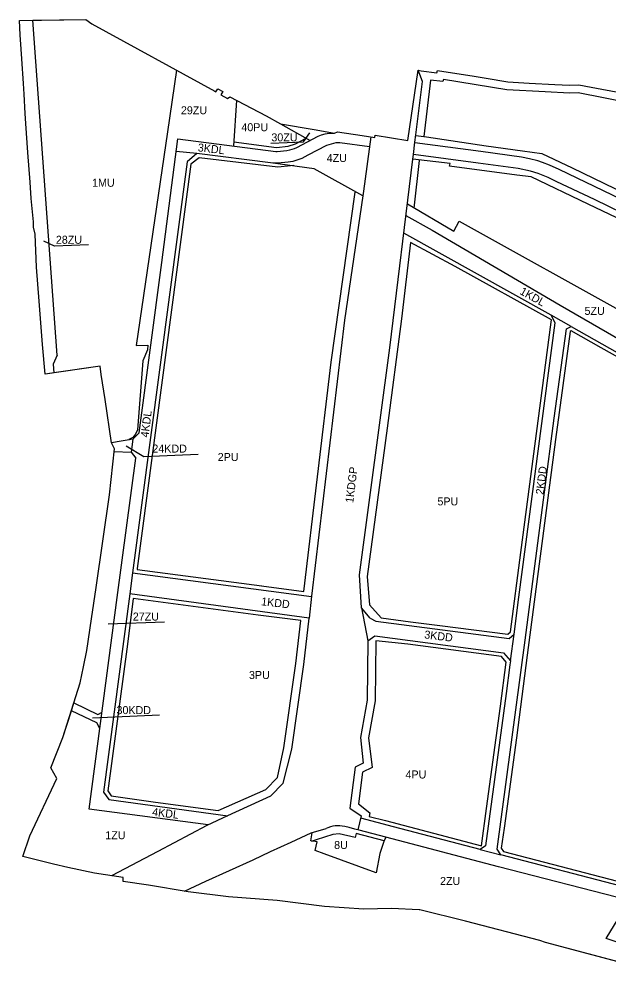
# Model space of a CAD drawing. Extents: x 7428203 to 7432868, y 5542672 to 5545406.
# Drawn here: x 7428203 to 7428940, y 5544072 to 5545281 of the extents above; entities that cross this region are included whole.
import ezdxf

# ---------------------------------------------------------------- set-up
doc = ezdxf.new("R2010")
doc.units = 0
for name, color, linetype in [('granica_planu', 7, 'Continuous'), ('linie_rozgraniczajace', 7, 'Continuous'), ('linie_zabudowy_nieprzekraczalne', 7, 'Continuous'), ('oznaczenia_przeznaczen', 7, 'Continuous')]:
    doc.layers.add(name, color=color, linetype=linetype)

msp = doc.modelspace()

# ---------------------------------------------------------------- linework, layer by layer
at = {"layer": 'granica_planu'}
msp.add_lwpolyline([(7428976.57, 5544096.41), (7428860.8, 5544127.52), (7428854.01, 5544130), (7428760.75, 5544154.04), (7428703.73, 5544168.24), (7428702.84, 5544168.29), (7428668.51, 5544170.04), (7428651.15, 5544169.49), (7428633.78, 5544168.93), (7428584.72, 5544172.19), (7428525.4, 5544180.04), (7428464.81, 5544184.55), (7428414.41, 5544190.57), (7428364.61, 5544199.09), (7428332.93, 5544203.75), (7428333.18, 5544208.54), (7428297.27, 5544213.91), (7428264.18, 5544221.13), (7428246.26, 5544225.05), (7428227.65, 5544229.82), (7428211.18, 5544234.03), (7428207.81, 5544234.91), (7428216.65, 5544260.74), (7428250.38, 5544332.47), (7428242.63, 5544345.7), (7428257.92, 5544383.71), (7428279.49, 5544451.84), (7428283.67, 5544472.01), (7428287.85, 5544492.18), (7428293.63, 5544531.64), (7428299.42, 5544571.11), (7428307.66, 5544628.99), (7428315.9, 5544686.88), (7428322.14, 5544744.45), (7428318.62, 5544751.58), (7428310.47, 5544805.9), (7428305.82, 5544836.94), (7428304.21, 5544847.68), (7428235.61, 5544837.59), (7428232.37, 5544874.57), (7428228.23, 5544928.73), (7428224.8, 5544971.21), (7428223.17, 5545012.45), (7428221.01, 5545021.19), (7428220.96, 5545027.72), (7428218.36, 5545057.21), (7428216.77, 5545077.57), (7428213.9, 5545114.42), (7428211.37, 5545150.6), (7428210.73, 5545163.13), (7428209.3, 5545187.57), (7428208.58, 5545200.8), (7428206.55, 5545231.54), (7428205.75, 5545243.51), (7428204.57, 5545261.47), (7428203.38, 5545279.44), (7428286.65, 5545280.95), (7428294.08, 5545275.54), (7428447.54, 5545191.05), (7428448.77, 5545190.38), (7428451.22, 5545194.3), (7428457.59, 5545190.79), (7428455.34, 5545186.6), (7428463.51, 5545182.06), (7428466.26, 5545184.02), (7428511.95, 5545160.26), (7428529.59, 5545150.37), (7428571.85, 5545143.2), (7428597.2, 5545138.9), (7428601.15, 5545140.18), (7428631.6, 5545135.8), (7428647.7, 5545133.49), (7428648.02, 5545136.23), (7428688.7, 5545129.56), (7428701.69, 5545217.27), (7428705.62, 5545216.46), (7428725.13, 5545214.15), (7428725.96, 5545217.18), (7428771.73, 5545209.75), (7428786.74, 5545207.32), (7428813.69, 5545202.94), (7428840.31, 5545201.4), (7428872.5, 5545199.53), (7428891.02, 5545198.75), (7428902.46, 5545199.05), (7428917.87, 5545196.3), (7428955.81, 5545189.3)], dxfattribs=at)
at = {"layer": 'linie_rozgraniczajace'}
for p, q in [((7428204.57, 5545261.47), (7428203.38, 5545279.44)), ((7428286.65, 5545280.95), (7428294.08, 5545275.54)), ((7428294.08, 5545275.54), (7428447.54, 5545191.05)), ((7428205.75, 5545243.51), (7428204.57, 5545261.47)), ((7428206.55, 5545231.54), (7428205.75, 5545243.51)), ((7428208.58, 5545200.8), (7428206.55, 5545231.54)), ((7428688.7, 5545129.56), (7428701.69, 5545217.27)), ((7428701.69, 5545217.27), (7428705.62, 5545216.46)), ((7428705.62, 5545216.46), (7428725.13, 5545214.15)), ((7428725.13, 5545214.15), (7428725.96, 5545217.18)), ((7428725.96, 5545217.18), (7428771.73, 5545209.75)), ((7428209.3, 5545187.57), (7428208.58, 5545200.8)), ((7428771.73, 5545209.75), (7428786.74, 5545207.32)), ((7428786.74, 5545207.32), (7428813.69, 5545202.94)), ((7428813.69, 5545202.94), (7428840.31, 5545201.4)), ((7428840.31, 5545201.4), (7428872.5, 5545199.53)), ((7428872.5, 5545199.53), (7428891.02, 5545198.75)), ((7428891.02, 5545198.75), (7428902.46, 5545199.05)), ((7428902.46, 5545199.05), (7428917.87, 5545196.3)), ((7428210.73, 5545163.13), (7428209.3, 5545187.57)), ((7428447.54, 5545191.05), (7428448.77, 5545190.38)), ((7428448.77, 5545190.38), (7428451.22, 5545194.3)), ((7428451.22, 5545194.3), (7428457.59, 5545190.79)), ((7428457.59, 5545190.79), (7428455.34, 5545186.6)), ((7428455.34, 5545186.6), (7428463.51, 5545182.06)), ((7428917.87, 5545196.3), (7428955.81, 5545189.3)), ((7428463.51, 5545182.06), (7428466.26, 5545184.02)), ((7428466.26, 5545184.02), (7428511.95, 5545160.26)), ((7428474.82, 5545179.57), (7428470.97, 5545122.84)), ((7428211.37, 5545150.6), (7428210.73, 5545163.13)), ((7428213.9, 5545114.42), (7428211.37, 5545150.6)), ((7428511.95, 5545160.26), (7428529.59, 5545150.37)), ((7428529.59, 5545150.37), (7428571.85, 5545143.2)), ((7428529.59, 5545150.37), (7428566.84, 5545129.46)), ((7428571.85, 5545143.2), (7428597.2, 5545138.9)), ((7428585.67, 5545137.9), (7428590.63, 5545138.64)), ((7428590.63, 5545138.64), (7428597.2, 5545138.9)), ((7428597.2, 5545138.9), (7428601.15, 5545140.18)), ((7428601.15, 5545140.18), (7428631.6, 5545135.8)), ((7428381.26, 5544977.16), (7428401.55, 5545131.8)), ((7428401.55, 5545131.8), (7428523.95, 5545116)), ((7428550.34, 5545120.73), (7428577, 5545134.84)), ((7428577, 5545134.84), (7428581.01, 5545136.68)), ((7428581.01, 5545136.68), (7428585.67, 5545137.9)), ((7428598.85, 5545126.59), (7428593.01, 5545124.97)), ((7428603.85, 5545126.69), (7428598.85, 5545126.59)), ((7428641.1, 5545121.81), (7428603.85, 5545126.69)), ((7428631.6, 5545135.8), (7428647.7, 5545133.49)), ((7428647.7, 5545133.49), (7428648.02, 5545136.23)), ((7428648.02, 5545136.23), (7428688.7, 5545129.56)), ((7428216.77, 5545077.57), (7428213.9, 5545114.42)), ((7428425.38, 5545113.27), (7428399.48, 5545115.99)), ((7428523.95, 5545116), (7428525.6, 5545116)), ((7428525.6, 5545116), (7428537.56, 5545117.17)), ((7428537.56, 5545117.17), (7428541.51, 5545117.82)), ((7428541.51, 5545117.82), (7428547.39, 5545119.75)), ((7428547.39, 5545119.75), (7428550.34, 5545120.73)), ((7428587.34, 5545123.25), (7428563.88, 5545111.05)), ((7428593.01, 5545124.97), (7428587.34, 5545123.25)), ((7428413.01, 5545102.98), (7428344.99, 5544589.32)), ((7428425.38, 5545113.27), (7428413.01, 5545102.98)), ((7428517.38, 5545101.52), (7428425.38, 5545113.27)), ((7428539.46, 5545102.28), (7428526.47, 5545101.12)), ((7428545.09, 5545103.21), (7428539.46, 5545102.28)), ((7428556.34, 5545106.91), (7428545.09, 5545103.21)), ((7428563.88, 5545111.05), (7428556.34, 5545106.91)), ((7428741.66, 5545100.69), (7428695.14, 5545106.15)), ((7428526.47, 5545101.12), (7428517.38, 5545101.52)), ((7428571.72, 5545094.34), (7428517.38, 5545101.52)), ((7428632.77, 5545060.49), (7428571.72, 5545094.34)), ((7428741.11, 5545097.37), (7428741.66, 5545100.69)), ((7428824.91, 5545086.26), (7428741.11, 5545097.37)), ((7428842.91, 5545084.32), (7428824.91, 5545086.26)), ((7428914.24, 5545050.13), (7428842.91, 5545084.32)), ((7428218.36, 5545057.21), (7428216.77, 5545077.57)), ((7428220.96, 5545027.72), (7428218.36, 5545057.21)), ((7428688.36, 5545050.58), (7428746.31, 5545016.37)), ((7429194.36, 5544914.89), (7428914.24, 5545050.13)), ((7428221.01, 5545021.19), (7428220.96, 5545027.72)), ((7428223.17, 5545012.45), (7428221.01, 5545021.19)), ((7428746.31, 5545016.37), (7428752.97, 5545028.91)), ((7428752.97, 5545028.91), (7429178.24, 5544792.55)), ((7428224.8, 5544971.21), (7428223.17, 5545012.45)), ((7428228.23, 5544928.73), (7428224.8, 5544971.21)), ((7428353.04, 5544764.26), (7428381.26, 5544977.16)), ((7428232.37, 5544874.57), (7428228.23, 5544928.73)), ((7428893.15, 5544897.22), (7428868.13, 5544911.33)), ((7428235.61, 5544837.59), (7428232.37, 5544874.57)), ((7428305.82, 5544836.94), (7428304.21, 5544847.68)), ((7428310.47, 5544805.9), (7428305.82, 5544836.94)), ((7428318.62, 5544751.58), (7428310.47, 5544805.9)), ((7428322.14, 5544744.45), (7428318.62, 5544751.58)), ((7428345.22, 5544756.14), (7428342.96, 5544740.16)), ((7428315.9, 5544686.88), (7428322.14, 5544744.45)), ((7428325.79, 5544558.62), (7428348.87, 5544732.75)), ((7428307.66, 5544628.99), (7428315.9, 5544686.88)), ((7428299.42, 5544571.11), (7428307.66, 5544628.99)), ((7428344.99, 5544589.32), (7428341.48, 5544562.94)), ((7428344.99, 5544589.32), (7428568.35, 5544559.65)), ((7428293.63, 5544531.64), (7428299.42, 5544571.11)), ((7428290.72, 5544294.07), (7428325.79, 5544558.62)), ((7428341.48, 5544562.94), (7428308.67, 5544315.36)), ((7428565.65, 5544532.84), (7428341.48, 5544562.94)), ((7428631.09, 5544545.61), (7428638.77, 5544504.44)), ((7428287.85, 5544492.18), (7428293.63, 5544531.64)), ((7428558.86, 5544474.65), (7428565.65, 5544532.84)), ((7428638.77, 5544504.44), (7428647.67, 5544510.77)), ((7428647.67, 5544510.77), (7428808.28, 5544489.37)), ((7428816.99, 5544479.53), (7428821.67, 5544512.69)), ((7428283.67, 5544472.01), (7428287.85, 5544492.18)), ((7428808.28, 5544489.37), (7428816.99, 5544479.53)), ((7428543.8, 5544369.15), (7428558.86, 5544474.65)), ((7428816.5, 5544474.34), (7428811.84, 5544438.61)), ((7428816.99, 5544479.53), (7428816.5, 5544474.34)), ((7428279.49, 5544451.84), (7428283.67, 5544472.01)), ((7428811.84, 5544438.61), (7428785.79, 5544248.05)), ((7428242.63, 5544345.7), (7428257.92, 5544383.71)), ((7428533.25, 5544326.63), (7428543.8, 5544369.15)), ((7428250.38, 5544332.47), (7428242.63, 5544345.7)), ((7428216.65, 5544260.74), (7428250.38, 5544332.47)), ((7428308.67, 5544315.36), (7428315.14, 5544306.06)), ((7428315.14, 5544306.06), (7428463.89, 5544285.68)), ((7428439.41, 5544274.21), (7428290.72, 5544294.07)), ((7428670.93, 5544272), (7428629.95, 5544282.69)), ((7428779.07, 5544243.6), (7428670.93, 5544272)), ((7428207.81, 5544234.91), (7428216.65, 5544260.74)), ((7428661.27, 5544258.91), (7428627.91, 5544267.68)), ((7428785.79, 5544248.05), (7428779.07, 5544243.6)), ((7428211.18, 5544234.03), (7428207.81, 5544234.91)), ((7428227.65, 5544229.82), (7428211.18, 5544234.03)), ((7428779.07, 5544243.6), (7428805.14, 5544236.81)), ((7428246.26, 5544225.05), (7428227.65, 5544229.82)), ((7428264.18, 5544221.13), (7428246.26, 5544225.05)), ((7428297.27, 5544213.91), (7428264.18, 5544221.13)), ((7428333.18, 5544208.54), (7428297.27, 5544213.91)), ((7428332.93, 5544203.75), (7428333.18, 5544208.54)), ((7428364.61, 5544199.09), (7428332.93, 5544203.75)), ((7428414.41, 5544190.57), (7428364.61, 5544199.09)), ((7428464.81, 5544184.55), (7428414.41, 5544190.57)), ((7428525.4, 5544180.04), (7428464.81, 5544184.55)), ((7428584.72, 5544172.19), (7428525.4, 5544180.04)), ((7428633.78, 5544168.93), (7428584.72, 5544172.19)), ((7428651.15, 5544169.49), (7428633.78, 5544168.93)), ((7428668.51, 5544170.04), (7428651.15, 5544169.49)), ((7428702.84, 5544168.29), (7428668.51, 5544170.04)), ((7428703.73, 5544168.24), (7428702.84, 5544168.29)), ((7428760.75, 5544154.04), (7428703.73, 5544168.24)), ((7428854.01, 5544130), (7428760.75, 5544154.04)), ((7428860.8, 5544127.52), (7428854.01, 5544130)), ((7428976.57, 5544096.41), (7428860.8, 5544127.52))]:
    msp.add_line(p, q, dxfattribs=at)
for points in [[(7428203.38, 5545279.44), (7428220.24, 5545279.74), (7428286.65, 5545280.95)], [(7428250.61, 5544861.39), (7428220.24, 5545279.74)], [(7428399.9, 5545217.28), (7428388.59, 5545140.59), (7428349.51, 5544873.25)], [(7428641.76, 5544532.47), (7428631.09, 5544545.61), (7428628.59, 5544586.69), (7428666.41, 5544870.56), (7428695.14, 5545106.15), (7428695.81, 5545111.93), (7428697.64, 5545127.52), (7428698.87, 5545136.61), (7428707.01, 5545203.48), (7428703.82, 5545211.9), (7428701.69, 5545217.27)], [(7428642.78, 5545134.2), (7428633.57, 5545066.36), (7428632.77, 5545060.49)], [(7429066.8, 5545002.44), (7428878, 5545093.23), (7428865.96, 5545098.79), (7428857.25, 5545102.2), (7428851.29, 5545104.05), (7428841.01, 5545106.72), (7428830.84, 5545108.91), (7428779.93, 5545116.01), (7428697.56, 5545126.83)], [(7428698.78, 5545135.91), (7428712.39, 5545133.97), (7428786.67, 5545123.07), (7428832.04, 5545116.79), (7428856.2, 5545113.43), (7428894.3, 5545095.54), (7429080.93, 5545005.11), (7429141.74, 5545005.48), (7429132.6, 5544978.04), (7429206.67, 5544942.98), (7429220.26, 5544939.2), (7429256.65, 5544938.86), (7429264.53, 5544938.12), (7429416.34, 5544933.1), (7429628, 5544926.11), (7429629.2, 5544929.06)], [(7428957.96, 5545038.3), (7428922.02, 5545055.69), (7428875.19, 5545077.96), (7428864.32, 5545083.13), (7428855.79, 5545086.67), (7428851.76, 5545088.25), (7428842, 5545091.16), (7428826.74, 5545094.39), (7428776.93, 5545101.29), (7428695.81, 5545111.93)], [(7428632.77, 5545060.49), (7428609.65, 5544905.04), (7428568.4, 5544560.19), (7428565.65, 5544532.84)], [(7428686.57, 5545035.92), (7428719.44, 5545017.6), (7428879.25, 5544923.88), (7428986.55, 5544861.55)], [(7428641.76, 5544532.47), (7428649.01, 5544528.76), (7428815.39, 5544507.44), (7428821.67, 5544512.69), (7428827.77, 5544559.05), (7428873.05, 5544901.71), (7428868.13, 5544911.33), (7428683.85, 5545013.62)], [(7429198.67, 5544727.47), (7429176.49, 5544739.59), (7429181.27, 5544730.14), (7429139.09, 5544411.72), (7429106.05, 5544162.35), (7429099.14, 5544157.86), (7428955.29, 5544197.85), (7428805.14, 5544236.81), (7428800.36, 5544244.12), (7428835.48, 5544505.35), (7428871.87, 5544782.58), (7428886.98, 5544894.27), (7428893.15, 5544897.22), (7428979.15, 5544848.51), (7428994.76, 5544839.83), (7428990.64, 5544827.77), (7428982.93, 5544761.65), (7428979.22, 5544729.83), (7429033.78, 5544721.61), (7429045.31, 5544798.17), (7429047.66, 5544810.44), (7429085.54, 5544789.39), (7429155.84, 5544750.87), (7429176.49, 5544739.59)], [(7428349.51, 5544873.25), (7428363.86, 5544873.81), (7428363.47, 5544867.85), (7428357.61, 5544854.27), (7428351.03, 5544768.14), (7428348.57, 5544762.51), (7428345.4, 5544758.61), (7428340.26, 5544755.89), (7428340.06, 5544755.29)], [(7428250.61, 5544861.39), (7428245.61, 5544849.98), (7428246.43, 5544839.18)], [(7428304.21, 5544847.68), (7428246.43, 5544839.18), (7428235.61, 5544837.59)], [(7428353.04, 5544764.26), (7428345.22, 5544756.14), (7428318.59, 5544751.76)], [(7428321.77, 5544740.99), (7428342.96, 5544740.16), (7428348.87, 5544732.75)], [(7428638.77, 5544504.44), (7428638.07, 5544430.1), (7428629.67, 5544383.68), (7428632.86, 5544351.61), (7428623.1, 5544346.62), (7428616.46, 5544295.36), (7428630.61, 5544285.45), (7428626.47, 5544268.06)], [(7428257.92, 5544383.71), (7428268.45, 5544416.97), (7428271.6, 5544426.92), (7428279.49, 5544451.84)], [(7428271.6, 5544426.92), (7428301.55, 5544412.33), (7428306.76, 5544415.07)], [(7428304.07, 5544394.81), (7428300.27, 5544402), (7428268.45, 5544416.97)], [(7428533.25, 5544326.63), (7428517.25, 5544310.17), (7428463.57, 5544285.54), (7428437.69, 5544273.41), (7428376.62, 5544241.05), (7428318.69, 5544210.71)], [(7428409.63, 5544191.39), (7428436.56, 5544203.82), (7428495.4, 5544230.51), (7428517.32, 5544241.22), (7428543.21, 5544252.82), (7428568.05, 5544264.25), (7428586.94, 5544269.96)], [(7428627.91, 5544267.68), (7428622.53, 5544269.1), (7428615.51, 5544270.93), (7428609.97, 5544272.15), (7428606.99, 5544272.71), (7428603.84, 5544273.06), (7428601.11, 5544273.16), (7428598.26, 5544273.05), (7428595.12, 5544272.7), (7428592.07, 5544272.11), (7428588.99, 5544270.86), (7428586.94, 5544269.96)], [(7428584.29, 5544238.12), (7428573.13, 5544242.21), (7428575.47, 5544253.06), (7428567.69, 5544254.25), (7428569.27, 5544264.61)], [(7429068.86, 5544072.19), (7429060.22, 5544098.67), (7429018.58, 5544105.27), (7428936.65, 5544132.38), (7428960.84, 5544171.8), (7428964.08, 5544180.06), (7428802.22, 5544221.94), (7428661.3, 5544258.99), (7428659.05, 5544253.72), (7428653.94, 5544238.67), (7428649.37, 5544214.38), (7428584.29, 5544238.12)]]:
    msp.add_lwpolyline(points, dxfattribs=at)
at = {"layer": 'linie_zabudowy_nieprzekraczalne'}
for p, q in [((7428471.31, 5545127.84), (7428524.74, 5545120.94)), ((7428548.38, 5545125.34), (7428561.66, 5545132.37)), ((7428524.74, 5545120.94), (7428539.34, 5545122.37)), ((7428539.34, 5545122.37), (7428548.38, 5545125.34)), ((7428703, 5545104.52), (7428696.16, 5545044.92)), ((7428868.54, 5544905.38), (7428748.02, 5544972.28)), ((7428830.05, 5544614.77), (7428868.1, 5544902.37)), ((7428868.1, 5544902.37), (7428868.54, 5544905.38)), ((7428817.03, 5544515.59), (7428830.05, 5544614.77)), ((7428345.67, 5544557.34), (7428338.36, 5544500.05)), ((7428501.72, 5544536.38), (7428345.67, 5544557.34)), ((7428692.19, 5544528.27), (7428728.65, 5544523.6)), ((7428728.65, 5544523.6), (7428813.86, 5544512.68)), ((7428813.86, 5544512.68), (7428817.03, 5544515.59)), ((7428338.36, 5544500.05), (7428313.91, 5544316.88)), ((7428805.77, 5544484.66), (7428688.67, 5544500.26)), ((7428804.62, 5544422.79), (7428811.81, 5544477.84)), ((7428811.81, 5544477.84), (7428805.77, 5544484.66)), ((7428787.13, 5544294.85), (7428804.62, 5544422.79)), ((7428313.91, 5544316.88), (7428318.23, 5544310.67)), ((7428318.23, 5544310.67), (7428373.45, 5544302.87)), ((7428373.45, 5544302.87), (7428451.93, 5544292.24)), ((7428780.78, 5544248.32), (7428787.13, 5544294.85)), ((7428660.94, 5544279.72), (7428780.78, 5544248.32))]:
    msp.add_line(p, q, dxfattribs=at)
for points in [[(7429616.61, 5544926.59), (7429647.45, 5545018.33), (7429649.37, 5545036.38), (7429583.9, 5545048.39), (7429433.03, 5545062.81), (7429282.53, 5545076.05), (7429087.37, 5545134.55), (7429047.91, 5545146.12), (7429048.68, 5545151.72), (7428964.03, 5545172.65), (7428964.84, 5545176.81), (7428901.68, 5545189.02), (7428890.94, 5545188.75), (7428860.63, 5545190.2), (7428812.6, 5545192.99), (7428733.24, 5545205.87), (7428732.51, 5545203.2), (7428717.24, 5545204.75), (7428708.73, 5545134.37)], [(7428546.29, 5545098.34), (7428526.58, 5545096.11), (7428428.21, 5545107.97), (7428417.72, 5545099.98), (7428350.75, 5544594.72), (7428350.76, 5544593.58), (7428506.32, 5544572.98)], [(7428506.1, 5544573.13), (7428558.94, 5544566.12), (7428593.25, 5544852.39), (7428623.16, 5545064.86)], [(7428748.02, 5544972.28), (7428692.26, 5545001.97), (7428681.15, 5544906.78), (7428662.98, 5544770.19), (7428638.03, 5544584.59), (7428640.88, 5544549.42), (7428655.43, 5544532.97), (7428692.19, 5544528.27)], [(7428451.93, 5544292.24), (7428511.38, 5544318.48), (7428526.08, 5544333.6), (7428533.9, 5544370.56), (7428548.96, 5544476.06), (7428555.27, 5544529.85), (7428501.72, 5544536.38)], [(7428688.67, 5544500.26), (7428648.77, 5544504.34), (7428648.06, 5544429.16), (7428639.76, 5544383.27), (7428644.19, 5544345.88), (7428632.34, 5544340.12), (7428627.2, 5544300.45), (7428641.18, 5544289.39), (7428640.6, 5544284.93), (7428660.94, 5544279.72)], [(7428624.48, 5544263.43), (7428622.94, 5544258.48), (7428603.12, 5544263.08), (7428595.04, 5544262.51), (7428574.28, 5544255.68), (7428568.09, 5544253.65)], [(7428659.32, 5544254.35), (7428624.48, 5544263.43), (7428624.48, 5544263.43)]]:
    msp.add_lwpolyline(points, dxfattribs=at)
msp.add_lwpolyline([(7428892.96, 5544891.59), (7428891.57, 5544890.93), (7428873.42, 5544756.02), (7428838.05, 5544486.51), (7428824.47, 5544383), (7428809.45, 5544270.11), (7428805.6, 5544245.24), (7428808.27, 5544241.17), (7428960.48, 5544201.62), (7429063.14, 5544173.58), (7429098.37, 5544163.32), (7429101.4, 5544165.29), (7429115.21, 5544269.13), (7429156.74, 5544584.47), (7429176.11, 5544729.27), (7429172.73, 5544735.95), (7429073.35, 5544790.45), (7428930.42, 5544870.37)], close=True, dxfattribs=at)
at = {"layer": 'oznaczenia_przeznaczen'}
for p, q in [((7428314.51, 5544525.39), (7428384.85, 5544528.24)), ((7428294.84, 5544408.27), (7428378.63, 5544411.67))]:
    msp.add_line(p, q, dxfattribs=at)
for points in [[(7428517.55, 5545126.15), (7428558.68, 5545127.82), (7428566.19, 5545139.18)], [(7428289.96, 5544999.35), (7428247.48, 5544997.62), (7428234.15, 5545003.69)], [(7428426.67, 5544737.07), (7428358.96, 5544734.32), (7428336.8, 5544747.48)]]:
    msp.add_lwpolyline(points, dxfattribs=at)

# ---------------------------------------------------------------- texts
for s, p in [('29ZU', (7428405.2828, 5545162.31)), ('40PU', (7428480.8428, 5545141.13)), ('30ZU', (7428518.3328, 5545128.47)), ('4ZU', (7428587.4859, 5545102.68)), ('1MU', (7428294.2764, 5545071.76)), ('28ZU', (7428249.0328, 5545000.51)), ('5ZU', (7428909.6759, 5544911.63)), ('24KDD', (7428369.6082, 5544739.56)), ('2PU', (7428451.3059, 5544729.05)), ('5PU', (7428725.8559, 5544673.58)), ('27ZU', (7428345.1828, 5544529.65)), ('3PU', (7428490.3359, 5544456.64)), ('30KDD', (7428324.8082, 5544412.76)), ('4PU', (7428685.9759, 5544332.32)), ('1ZU', (7428310.8159, 5544256.41)), ('8U', (7428596.7441, 5544244.22)), ('2ZU', (7428729.1459, 5544199.24))]:
    msp.add_text(s, height=10, dxfattribs=at).set_placement(p)
for s, rotation, p in [('3KDL', 353.4039733, (7428426.0008, 5545116.1252)), ('1KDL', 330.8923818, (7428827.853, 5544938.1401)), ('4KDL', 83.07288, (7428364.7744, 5544758.116)), ('1KDGP', 83.07288, (7428620.6078, 5544676.1838)), ('2KDD', 83.07288, (7428858.5237, 5544686.462)), ('1KDD', 353.6446752, (7428505.2172, 5544548.8118)), ('3KDD', 353.07288, (7428708.992, 5544507.4563)), ('4KDL', 353.07288, (7428368.956, 5544285.8756))]:
    msp.add_text(s, height=10, rotation=rotation, dxfattribs=at).set_placement(p)

doc.saveas('drawing.dxf')
